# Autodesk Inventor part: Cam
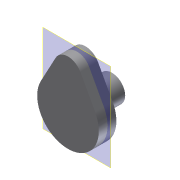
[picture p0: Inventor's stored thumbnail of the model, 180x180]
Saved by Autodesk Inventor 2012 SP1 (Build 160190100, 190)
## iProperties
Created: 2006-03
Part Number: Cam
Document SubType Name: Modeling
Mass: 14.1538 g
Surface Area: 42.5457 cm^2
Volume: 14.1538 cm^3
Density: 1 g/cm^3
Material: Default
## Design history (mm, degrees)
sketch "Sketch1"
  geometry: L1 (0, -22.05)-(0, 41.65) reference; L2 (-28, 0)-(21, 0) reference; L3 (-15.4, 8.312)-(-7.04, 23.8); L4 (7.04, 23.8)-(15.4, 8.312); A1 r 17.5 centre (0, 0) between (-15.4, 8.312) and (15.4, 8.312); A2 r 8 centre (0, 20) between (7.04, 23.8) and (-7.04, 23.8); 1 further point
  constraints: 4 end point, 4 point on circle, 4 tangent, 2 centre point, 1 coincident, 1 point on line
  dimensions: "d0" = 20 distance of point (0, 0) A2.centre; "d1" = 8 radius of A2; "d2" = 17.5 radius of A1
extrude "Extrusion1" new body sketch "Sketch1" distance "d3" = 10; taper "d4" = 0 deg
sketch "Sketch2"
  geometry: C1 r 7.5 at (0, 0); 1 further point
  constraints: 1 centre point, 1 coincident
  dimensions: "d5" = 15 diameter of C1
extrude "Extrusion2" join sketch "Sketch2" distance "d6" = 15; taper "d7" = 0 deg
workplane "Work Plane2"
body "Solid1"
